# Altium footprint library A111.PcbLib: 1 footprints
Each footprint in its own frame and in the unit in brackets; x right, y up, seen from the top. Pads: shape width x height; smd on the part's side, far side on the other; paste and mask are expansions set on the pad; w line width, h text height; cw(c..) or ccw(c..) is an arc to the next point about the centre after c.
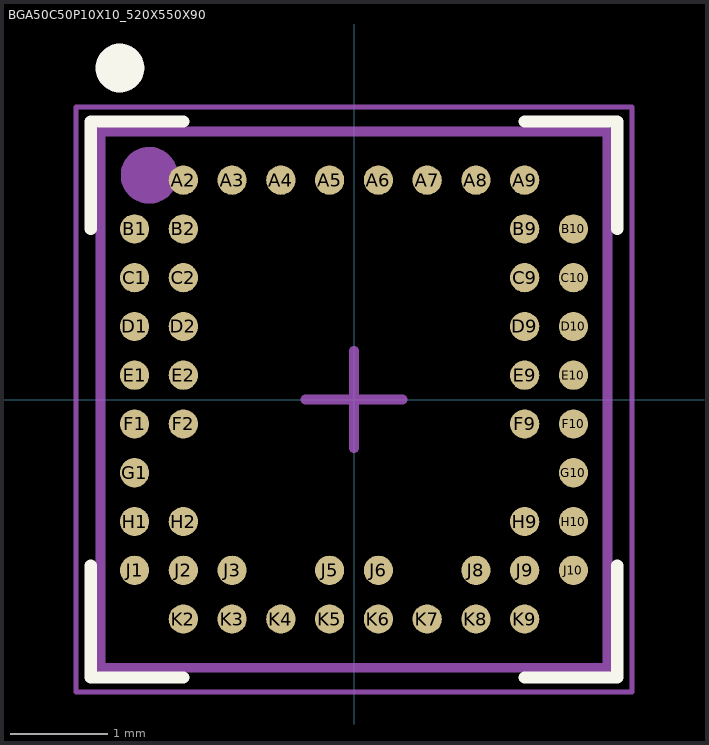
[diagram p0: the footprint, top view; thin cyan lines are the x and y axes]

## BGA50C50P10X10_520X550X90 [mm]
pads (50):
  round 0.3 smd paste-0.05 mask+0.05: A2(-1.75,2.25) A3(-1.25,2.25) A4(-0.75,2.25) A5(-0.25,2.25) A6(0.25,2.25) A7(0.75,2.25) A8(1.25,2.25) A9(1.75,2.25) B1(-2.25,1.75) B2(-1.75,1.75) B9(1.75,1.75) B10(2.25,1.75) C1(-2.25,1.25) C2(-1.75,1.25) C9(1.75,1.25) C10(2.25,1.25) D1(-2.25,0.75) D2(-1.75,0.75) D9(1.75,0.75) D10(2.25,0.75) E1(-2.25,0.25) E2(-1.75,0.25) E9(1.75,0.25) E10(2.25,0.25) F1(-2.25,-0.25) F2(-1.75,-0.25) F9(1.75,-0.25) F10(2.25,-0.25) G1(-2.25,-0.75) G10(2.25,-0.75) H1(-2.25,-1.25) H2(-1.75,-1.25) H9(1.75,-1.25) H10(2.25,-1.25) J1(-2.25,-1.75) J2(-1.75,-1.75) J3(-1.25,-1.75) J5(-0.25,-1.75) J6(0.25,-1.75) J8(1.25,-1.75) J9(1.75,-1.75) J10(2.25,-1.75) K2(-1.75,-2.25) K3(-1.25,-2.25) K4(-0.75,-2.25) K5(-0.25,-2.25) K6(0.25,-2.25) K7(0.75,-2.25) K8(1.25,-2.25) K9(1.75,-2.25)
Top Overlay:
  circle w0.25: c-2.4,3.4 r0.125
  lines w0.125: -2.7,-1.7 -2.7,-2.85 -1.75,-2.85 ; -2.7,1.75 -2.7,2.85 -1.75,2.85 ; 1.75,-2.85 2.7,-2.85 2.7,-1.7 ; 1.75,2.85 2.7,2.85 2.7,1.75
Top Courtyard:
  lines w0.05: -2.85,-3 2.85,-3 2.85,3 -2.85,3 -2.85,-3
  lines w0.1: -0.5,0 0.5,0 ; 0,-0.5 0,0.5
Top Assembly:
  circle w0.3: c-2.1,2.3 r0.141
  lines w0.1: -2.6,-2.75 2.6,-2.75 2.6,2.75 -2.6,2.75 -2.6,-2.75
  text ".Designator" at -2.25,-0.374 h2
3D body "A111_dark v1.step": height 0.51, standoff 0, extent -2.602,-2.75 2.602,2.75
